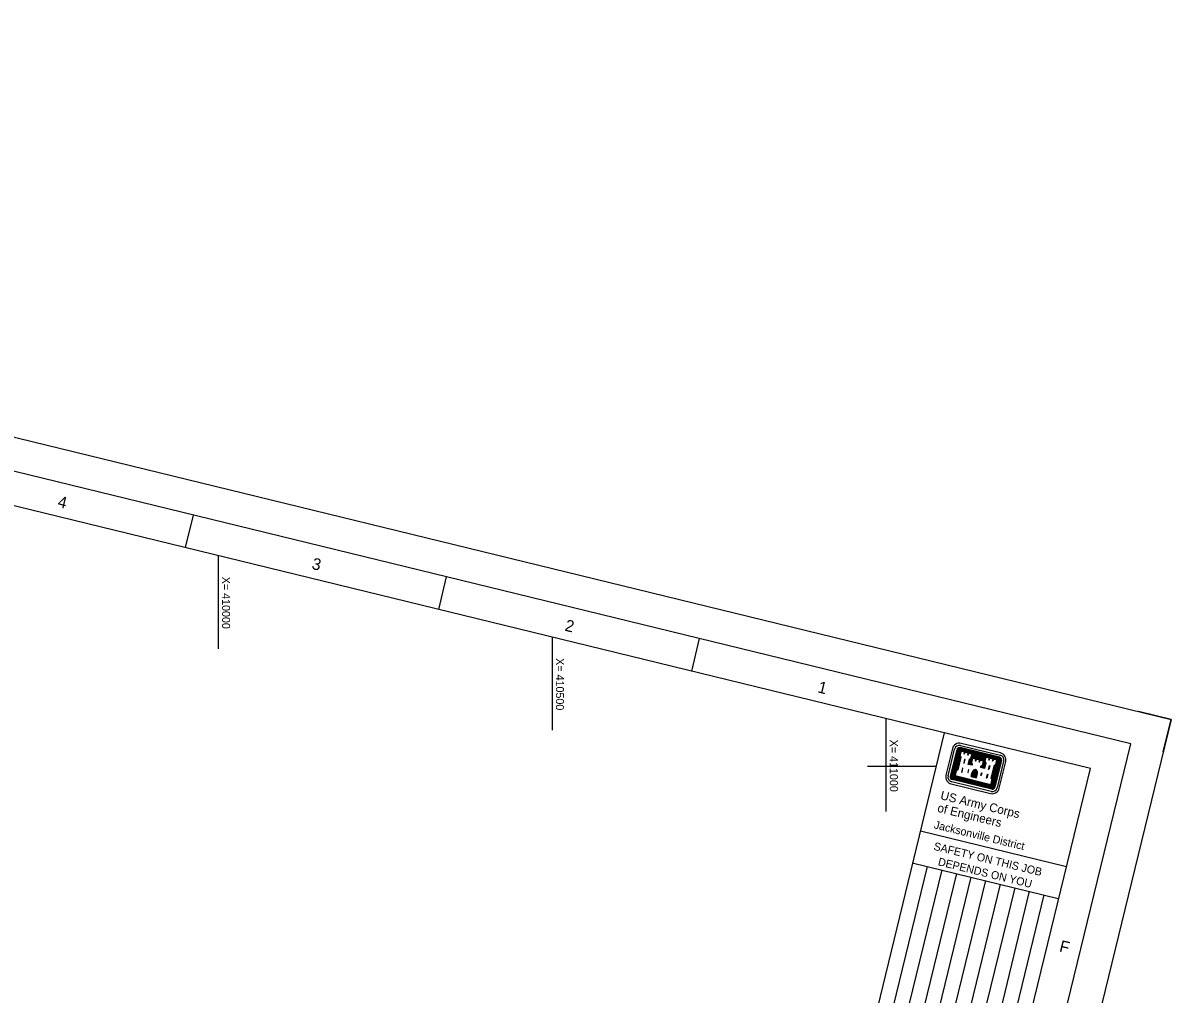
# Model space of a CAD drawing. Extents: x 406346 to 411426, y 1189267 to 1193612.
# Drawn here: x 409707 to 411426, y 1192159 to 1193612 of the extents above; entities that cross this region are included whole.
import ezdxf

# ---------------------------------------------------------------- set-up
doc = ezdxf.new("R2010")
doc.units = 0
for name, color, linetype in [('G-ANNO-NPLT', 7, 'Continuous'), ('G-ANNO-TEXT-LOGO', 7, 'Continuous'), ('G-ANNO-TEXT-TTLB', 7, 'Continuous'), ('G-ANNO-TTLB', 7, 'Continuous'), ('V-TOPO-COOR-STAT', 7, 'Continuous')]:
    doc.layers.add(name, color=color, linetype=linetype)

msp = doc.modelspace()

# ---------------------------------------------------------------- linework, layer by layer
at = {"layer": 'G-ANNO-NPLT'}
msp.add_lwpolyline([(407151.7, 1193612.5), (411426.4, 1192570), (410620.9, 1189266.8), (406346.2, 1190309.3)], close=True, dxfattribs=at)
msp.add_lwpolyline([(411414.6, 1192521.4), (411426.4, 1192570), (411377.8, 1192581.8)], dxfattribs=at)
at = {"layer": 'G-ANNO-TEXT-LOGO'}
for p, q in [((411099.1, 1192526.2), (411089.4, 1192486.4)), ((411092.5, 1192485.6), (411102.2, 1192525.5)), ((411105.6, 1192524.6), (411095.9, 1192484.8)), ((411106.5, 1192524.4), (411096.8, 1192484.6)), ((411107.2, 1192524.2), (411097.5, 1192484.4)), ((411108.1, 1192524), (411098.4, 1192484.2)), ((411109, 1192523.8), (411099.3, 1192484)), ((411109.9, 1192523.6), (411100.2, 1192484)), ((411110.6, 1192523.4), (411101.2, 1192484.7)), ((411168.7, 1192509.9), (411109.6, 1192524.3)), ((411168.9, 1192510.7), (411109.8, 1192525.1)), ((411169.1, 1192511.5), (411110, 1192525.9)), ((411169.3, 1192512.4), (411110.2, 1192526.8)), ((411169.5, 1192513.3), (411110.4, 1192527.7)), ((411111.3, 1192531), (411170.3, 1192516.6)), ((411171.1, 1192519.7), (411112, 1192534.1)), ((411129.7, 1192517.6), (411147.8, 1192513.2)), ((411129.9, 1192518.5), (411148, 1192514.1)), ((411109.3, 1192514.8), (411104.3, 1192494.4)), ((411109.9, 1192513.7), (411105.4, 1192495.1)), ((411128.7, 1192513.4), (411146.8, 1192509)), ((411128.9, 1192514.3), (411147, 1192509.9)), ((411129.1, 1192515.1), (411147.2, 1192510.7)), ((411129.3, 1192516), (411147.4, 1192511.6)), ((411129.5, 1192516.8), (411147.6, 1192512.4)), ((411167.4, 1192509.6), (411158, 1192470.9)), ((411168.2, 1192509.4), (411158.5, 1192469.8)), ((411163.6, 1192500.6), (411159, 1192482.1)), ((411169, 1192509.2), (411159.3, 1192469.3)), ((411164.6, 1192501.2), (411159.7, 1192481)), ((411169.9, 1192508.9), (411160.2, 1192469.1)), ((411170.7, 1192508.8), (411161, 1192468.9)), ((411171.6, 1192508.5), (411161.8, 1192468.7)), ((411172.4, 1192508.3), (411162.7, 1192468.5)), ((411175.7, 1192507.5), (411166, 1192467.7)), ((411169.2, 1192466.9), (411178.9, 1192506.7)), ((411158.7, 1192468.9), (411099.6, 1192483.3)), ((411158.5, 1192469.8), (411100.2, 1192484)), ((411158, 1192470.9), (411101.2, 1192484.7)), ((411127.1, 1192484.5), (411128.7, 1192491)), ((411127.1, 1192484.5), (411134.9, 1192482.6)), ((411127.9, 1192484.3), (411129.5, 1192490.8)), ((411128.7, 1192484.1), (411130.3, 1192490.6)), ((411129.6, 1192483.9), (411131.2, 1192490.4)), ((411130.4, 1192483.7), (411132, 1192490.2)), ((411131.6, 1192483.4), (411133.2, 1192489.9)), ((411132.3, 1192483.2), (411133.9, 1192489.7)), ((411133.2, 1192483), (411134.8, 1192489.5)), ((411134.1, 1192482.8), (411135.7, 1192489.3)), ((411134.9, 1192482.6), (411136.5, 1192489.1)), ((411097.2, 1192473.4), (411156.3, 1192459)), ((411157.1, 1192462.2), (411098, 1192476.6)), ((411157.9, 1192465.6), (411098.8, 1192480)), ((411158.1, 1192466.3), (411099, 1192480.7)), ((411158.3, 1192467.2), (411099.2, 1192481.6)), ((411158.5, 1192468.1), (411099.4, 1192482.5))]:
    msp.add_line(p, q, dxfattribs=at)
for points in [[(411111.3, 1192523.2), (411109.5, 1192515.6), (411110.7, 1192513.5), (411106.2, 1192494.9), (411104.1, 1192493.6), (411102, 1192485.2), (411157.4, 1192471.6), (411159.5, 1192480.1), (411158.2, 1192482.3), (411162.7, 1192500.8), (411164.8, 1192502.1), (411166.7, 1192509.7), (411159.4, 1192511.5), (411153.8, 1192512.9), (411148.5, 1192514.2), (411146.7, 1192506.5), (411148.1, 1192504.4), (411146.4, 1192497.6), (411142.4, 1192498.6), (411142.5, 1192499.3), (411144.7, 1192500.6), (411146.6, 1192508.2), (411139.3, 1192509.9), (411133.6, 1192511.3), (411128.5, 1192512.6), (411126.6, 1192505), (411128, 1192502.8), (411127.8, 1192502.1), (411123.7, 1192503.1), (411125.4, 1192509.9), (411127.5, 1192511.2), (411129.4, 1192518.8), (411122.1, 1192520.6), (411116.5, 1192522), (411111.3, 1192523.2)], [(411111.9, 1192522.2), (411110.3, 1192515.8), (411111.6, 1192513.6), (411107, 1192494.3), (411104.8, 1192493), (411103, 1192485.8), (411156.8, 1192472.7), (411158.6, 1192479.9), (411157.2, 1192482.1), (411161.9, 1192501.3), (411164.1, 1192502.6), (411165.7, 1192509), (411160.5, 1192510.3), (411159.7, 1192507.3), (411159.2, 1192507.4), (411160, 1192510.4), (411154.8, 1192511.7), (411154.1, 1192508.7), (411153.7, 1192508.8), (411154.4, 1192511.8), (411149.2, 1192513.1), (411147.6, 1192506.7), (411149, 1192504.5), (411147, 1192496.6), (411141.4, 1192498), (411141.8, 1192499.8), (411144, 1192501.2), (411145.6, 1192507.6), (411140.3, 1192508.8), (411139.6, 1192505.8), (411139.2, 1192505.9), (411140, 1192508.9), (411134.7, 1192510.2), (411134, 1192507.2), (411133.5, 1192507.3), (411134.2, 1192510.3), (411129.1, 1192511.6), (411127.5, 1192505.2), (411128.8, 1192503), (411128.4, 1192501.2), (411122.7, 1192502.5), (411124.7, 1192510.4), (411126.8, 1192511.7), (411128.4, 1192518.1), (411123.3, 1192519.4), (411122.5, 1192516.4), (411122, 1192516.5), (411122.8, 1192519.5), (411117.5, 1192520.8), (411116.8, 1192517.8), (411116.4, 1192517.9), (411117.1, 1192520.9), (411111.9, 1192522.2)], [(411117.3, 1192509.8), (411115.9, 1192504.2), (411116.5, 1192504.1), (411117.9, 1192509.7), (411117.3, 1192509.8)], [(411126.8, 1192509.7), (411126.1, 1192509.3), (411124.8, 1192503.8), (411126.6, 1192503.3), (411125.7, 1192504.9), (411126.9, 1192509.8)], [(411146.8, 1192504.8), (411147.1, 1192504.2), (411145.8, 1192498.7), (411144, 1192499.1), (411145.5, 1192500.1), (411146.7, 1192504.9)], [(411155.1, 1192500.6), (411153.7, 1192495), (411153.3, 1192495.1), (411154.6, 1192500.7), (411155.1, 1192500.6)], [(411114.2, 1192496.9), (411112.8, 1192491.2), (411113.4, 1192491), (411114.8, 1192496.8), (411114.2, 1192496.9)], [(411123.1, 1192494.7), (411122.1, 1192490.7), (411122.6, 1192490.6), (411123.6, 1192494.6), (411123.1, 1192494.7)], [(411143.1, 1192489.9), (411142.1, 1192485.9), (411141.7, 1192486), (411142.6, 1192490), (411143.1, 1192489.9)], [(411152, 1192487.7), (411150.6, 1192482), (411150.1, 1192482.1), (411151.5, 1192487.8), (411152, 1192487.7)]]:
    msp.add_lwpolyline(points, dxfattribs=at)
for centre, major_axis, start_param, end_param in [((411109.5, 1192523.7), (10.4, -2.5), 1.57078, 3.141576), ((411109.5, 1192523.7), (7.28, -1.77), 1.57078, 3.141576), ((411109.5, 1192523.7), (3.9, -0.95), 1.57078, 3.141576), ((411109.5, 1192523.7), (3.06, -0.75), 1.57078, 3.141576), ((411109.5, 1192523.7), (2.22, -0.54), 1.57078, 3.141576), ((411109.5, 1192523.7), (1.37, -0.33), 1.57078, 3.141576), ((411109.5, 1192523.7), (0.53, -0.129), 1.57078, 3.141576), ((411168.5, 1192509.3), (10.4, -2.5), 6.283169, 7.853965), ((411168.5, 1192509.3), (0.53, -0.129), 6.283169, 7.853965), ((411168.5, 1192509.3), (1.37, -0.33), 6.283169, 7.853965), ((411168.5, 1192509.3), (2.22, -0.54), 6.283169, 7.853965), ((411168.5, 1192509.3), (3.06, -0.75), 6.283169, 7.853965), ((411168.5, 1192509.3), (3.9, -0.95), 6.283169, 7.853965), ((411168.5, 1192509.3), (7.28, -1.77), 6.28317, 7.853966), ((411099.8, 1192483.8), (-10.4, 2.5), 6.28317, 7.853966), ((411099.8, 1192483.8), (-7.28, 1.77), 6.28317, 7.853966), ((411099.8, 1192483.8), (-3.9, 0.95), 6.28317, 7.853966), ((411099.8, 1192483.8), (-3.06, 0.75), 6.28317, 7.853966), ((411099.8, 1192483.8), (-2.22, 0.54), 6.28317, 7.853966), ((411099.8, 1192483.8), (-1.37, 0.33), 6.28317, 7.853966), ((411099.8, 1192483.8), (-0.53, 0.129), 6.28317, 7.853966), ((411133.9, 1192489.3), (-5.4, 1.32), 4.985832, 6.214359), ((411133.9, 1192489.3), (-4.55, 1.11), 4.947465, 6.21436), ((411133.9, 1192489.3), (-3.71, 0.9), 4.947465, 6.21436), ((411133.9, 1192489.3), (-2.87, 0.7), 4.947465, 6.21436), ((411131, 1192490), (2.02, -0.49), 0.068794, 1.335689), ((411133.9, 1192489.3), (-2.02, 0.49), 4.947465, 6.214359), ((411131, 1192490), (2.87, -0.7), 0.068794, 1.335689), ((411131, 1192490), (3.71, -0.9), 0.068795, 1.335689), ((411131, 1192490), (4.55, -1.11), 0.068795, 1.335689), ((411131, 1192490), (5.4, -1.32), 0.068795, 1.29842), ((411158.8, 1192469.4), (10.4, -2.5), 4.712373, 6.28317), ((411158.8, 1192469.4), (-7.28, 1.77), 1.570781, 3.141577), ((411158.8, 1192469.4), (3.9, -0.95), 4.712373, 6.28317), ((411158.8, 1192469.4), (3.06, -0.75), 4.712373, 6.28317), ((411158.8, 1192469.4), (2.22, -0.54), 4.712373, 6.28317), ((411158.8, 1192469.4), (1.37, -0.33), 4.712373, 6.28317), ((411158.8, 1192469.4), (0.53, -0.129), 4.712373, 6.28317)]:
    msp.add_ellipse(centre, major_axis=major_axis, ratio=0.99964, start_param=start_param, end_param=end_param, dxfattribs=at)
at = {"layer": 'G-ANNO-TTLB'}
for p, q in [((409962.1, 1192875.6), (409950.3, 1192827.1)), ((410341, 1192783.2), (410329.2, 1192734.7)), ((410719.9, 1192690.8), (410708.1, 1192642.2)), ((411086.9, 1192549.9), (410328.8, 1189441)), ((411051.1, 1192402.9), (411269.7, 1192349.6)), ((411061.2, 1192349.9), (410862.7, 1191535.9)), ((411038.9, 1192355.3), (411257.5, 1192302)), ((411083, 1192344.6), (410884.5, 1191530.5)), ((411104.9, 1192339.3), (410906.4, 1191525.2)), ((411126.8, 1192333.9), (410928.2, 1191519.9)), ((411148.6, 1192328.6), (410950.1, 1191514.5)), ((411170.5, 1192323.3), (410971.9, 1191509.2)), ((411192.3, 1192317.9), (410993.8, 1191503.9)), ((411214.2, 1192312.6), (411015.7, 1191498.5)), ((411236.1, 1192307.3), (411037.5, 1191493.2))]:
    msp.add_line(p, q, dxfattribs=at)
for points in [[(406406.6, 1190346), (410584.1, 1189327.2), (411366, 1192533.3), (407188.5, 1193552.1)], [(411305.6, 1192496.5), (407298, 1193473.9), (406539.9, 1190365), (410547.4, 1189387.7)]]:
    msp.add_lwpolyline(points, close=True, dxfattribs=at)
at = {"layer": 'V-TOPO-COOR-STAT'}
for p, q in [((410000, 1192675.7), (410000, 1192814.7)), ((410500, 1192553.8), (410500, 1192692.7)), ((411000, 1192431.9), (411000, 1192570.8)), ((410971.9, 1192500), (411074.8, 1192500))]:
    msp.add_line(p, q, dxfattribs=at)

# ---------------------------------------------------------------- texts
at = {"layer": 'G-ANNO-TEXT-TTLB'}
for s, height, p in [('US Army Corps', 13.086, (411080.2, 1192450.6)), ('of Engineers', 13.086, (411075.6, 1192431.8)), ('Jacksonville District', 11.9, (411070.6, 1192407)), ('SAFETY ON THIS JOB', 11.9, (411070.1, 1192374.8)), ('DEPENDS ON YOU', 11.9, (411076.6, 1192351.7))]:
    msp.add_text(s, height=height, rotation=346.2946, dxfattribs=at).set_placement(p)
at = {"layer": 'G-ANNO-TTLB'}
for s, p in [('4', (409758, 1192888.2)), ('3', (410138.6, 1192795.4)), ('2', (410517.5, 1192703)), ('1', (410896.3, 1192610.6)), ('F', (411258.1, 1192222.7))]:
    msp.add_text(s, height=17.5, rotation=346.2946, dxfattribs=at).set_placement(p)
at = {"layer": 'V-TOPO-COOR-STAT'}
for s, p in [('X= 410000', (410005.3, 1192783.5)), ('X= 410500', (410505.3, 1192661.6)), ('X= 411000', (411005.3, 1192539.6))]:
    msp.add_text(s, height=12, rotation=270, dxfattribs=at).set_placement(p)

doc.saveas('drawing.dxf')
